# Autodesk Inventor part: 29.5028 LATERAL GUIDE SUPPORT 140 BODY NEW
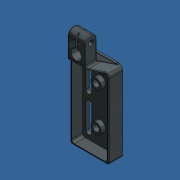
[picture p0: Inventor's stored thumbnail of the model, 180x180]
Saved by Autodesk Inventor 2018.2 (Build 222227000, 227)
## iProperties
Part Number: 29.5028 LATERAL GUIDE SUPPORT 140 BODY NEW
Material: Generic
Document SubType Name: Modeling
Designer: amoles
Appearance: Generic
Author: amoles
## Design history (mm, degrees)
feature "Volumenkörper1"
body "Solid1"
